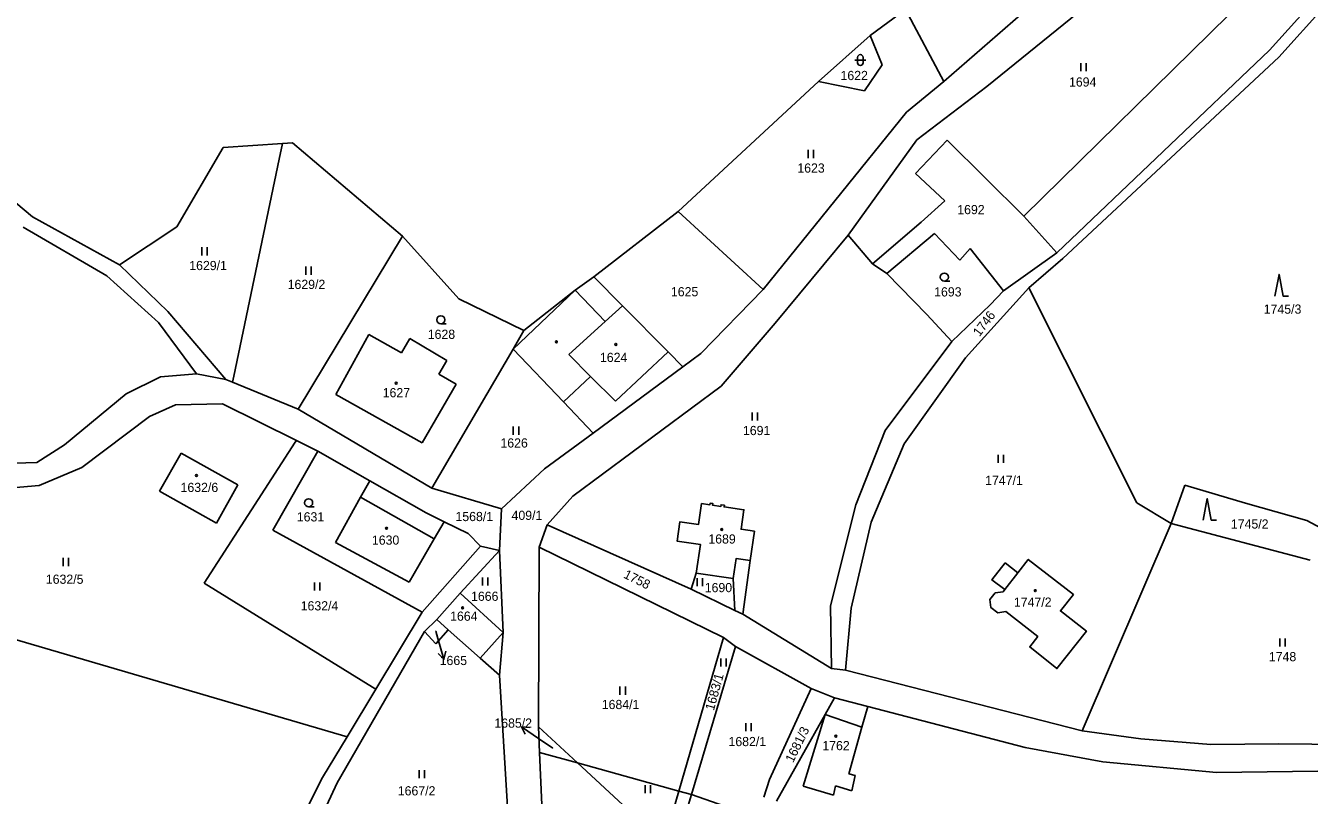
# Model space of a CAD drawing. Extents: x -670359 to -668019, y -978807 to -976674.
# Drawn here: x -669138.3 to -668901.1, y -978192.9 to -978050.6 of the extents above; entities that cross this region are included whole.
import ezdxf

# ---------------------------------------------------------------- set-up
doc = ezdxf.new("R2010")
doc.units = 0
for name, color, linetype in [('Hranice parcel', 7, 'Continuous'), ('Parcelní čísla', 7, 'Continuous'), ('Vnitřní kresba', 7, 'Continuous'), ('Značky budov', 7, 'Continuous'), ('Značky kultur', 7, 'Continuous')]:
    doc.layers.add(name, color=color, linetype=linetype)

msp = doc.modelspace()

# ---------------------------------------------------------------- linework, layer by layer
at = {"layer": 'Hranice parcel'}
for points in [[(-668936, -978032.58), (-668968.61, -978060.99)], [(-668908.45, -978055.15), (-668888.87, -978033.49)], [(-668930.88, -978037.71), (-668960.68, -978061.9)], [(-668906.72, -978056.46), (-668898.28, -978047.1)], [(-668975.67, -978047.64), (-668982.21, -978052.45)], [(-668968.61, -978060.99), (-668975.67, -978047.64)], [(-668953.8, -978085.85), (-668915.95, -978048.61)], [(-668982.21, -978052.45), (-668991.74, -978060.98)], [(-668980.02, -978057.91), (-668982.21, -978052.45)], [(-668947.71, -978092.62), (-668908.45, -978055.15)], [(-668946.62, -978093.71), (-668906.72, -978056.46)], [(-668983.27, -978062.67), (-668980.02, -978057.91)], [(-668991.74, -978060.98), (-669017.69, -978085.02)], [(-668991.74, -978060.98), (-668983.27, -978062.67)], [(-668975.47, -978066.6), (-668968.61, -978060.99)], [(-668960.68, -978061.9), (-668973.6, -978071.73)], [(-668975.47, -978066.6), (-669001.99, -978099.42)], [(-669153.63, -978072.03), (-669136.97, -978085.97)], [(-669110.34, -978087.85), (-669101.78, -978073.15)], [(-669101.78, -978073.15), (-669090.82, -978072.45)], [(-669090.82, -978072.45), (-669091.42, -978075.32)], [(-669088.96, -978072.33), (-669090.82, -978072.45)], [(-669088.96, -978072.33), (-669068.65, -978089.58)], [(-668986.28, -978089.35), (-668973.6, -978071.73)], [(-668967.97, -978071.78), (-668973.84, -978077.99)], [(-668967.97, -978071.78), (-668953.8, -978085.85)], [(-669091.42, -978075.32), (-669099.81, -978115.46)], [(-668973.84, -978077.99), (-668968.41, -978083.05)], [(-668968.41, -978083.05), (-668972.8, -978086.97)], [(-669017.69, -978085.02), (-669033.27, -978097.05)], [(-669017.69, -978085.02), (-669001.99, -978099.42)], [(-669136.97, -978085.97), (-669120.9, -978094.86)], [(-668981.81, -978094.65), (-668972.8, -978086.97)], [(-668953.8, -978085.85), (-668947.71, -978092.62)], [(-669123.24, -978096.91), (-669138.75, -978087.87)], [(-669120.9, -978094.86), (-669110.34, -978087.85)], [(-669068.65, -978089.58), (-669087.88, -978121.53)], [(-669058.21, -978101.14), (-669068.65, -978089.58)], [(-668986.28, -978089.35), (-668999.74, -978105.61)], [(-668981.81, -978094.65), (-668986.28, -978089.35)], [(-668970.35, -978089.09), (-668979.15, -978096.47)], [(-668965.63, -978093.97), (-668970.35, -978089.09)], [(-668963.76, -978091.85), (-668965.63, -978093.97)], [(-668957.56, -978099.63), (-668963.76, -978091.85)], [(-669120.9, -978094.86), (-669112.02, -978103.51)], [(-668979.15, -978096.47), (-668981.81, -978094.65)], [(-668957.56, -978099.63), (-668947.71, -978092.62)], [(-668952.92, -978099.08), (-668946.62, -978093.71)], [(-669113.72, -978105.49), (-669123.24, -978096.91)], [(-669033.27, -978097.05), (-669036.74, -978099.53)], [(-669033.27, -978097.05), (-669027.96, -978102.42)], [(-668971.73, -978104.03), (-668979.15, -978096.47)], [(-669036.74, -978099.53), (-669046.18, -978107.02)], [(-669001.99, -978099.42), (-669013.49, -978111.22)], [(-668964.59, -978112.07), (-668952.92, -978099.08)], [(-668960.07, -978102.25), (-668957.56, -978099.63)], [(-668952.92, -978099.08), (-668932.95, -978138.87)], [(-669046.18, -978107.02), (-669058.21, -978101.14)], [(-669112.02, -978103.51), (-669101.27, -978116.03)], [(-669027.96, -978102.42), (-669019.57, -978110.91)], [(-668967.11, -978109), (-668971.73, -978104.03)], [(-668967.11, -978109), (-668960.07, -978102.25)], [(-669106.7, -978115.01), (-669113.72, -978105.49)], [(-668999.74, -978105.61), (-669009.75, -978117.26)], [(-669080.97, -978118.81), (-669074.84, -978107.75)], [(-669074.84, -978107.75), (-669068.84, -978111.15)], [(-669068.84, -978111.15), (-669067.25, -978108.48)], [(-669067.25, -978108.48), (-669060.41, -978112.55)], [(-669046.18, -978107.02), (-669048.18, -978110.44)], [(-668979.46, -978125.5), (-668967.11, -978109)], [(-669048.18, -978110.44), (-669063.22, -978136.11)], [(-669038.91, -978120.18), (-669048.18, -978110.44)], [(-669019.57, -978110.91), (-669016.82, -978113.68)], [(-669013.49, -978111.22), (-669016.82, -978113.68)], [(-669060.41, -978112.55), (-669061.91, -978115.07)], [(-669016.82, -978113.68), (-669033.42, -978125.96)], [(-668975.91, -978127.95), (-668964.59, -978112.07)], [(-669113.35, -978115.58), (-669119.71, -978118.71)], [(-669106.7, -978115.01), (-669113.35, -978115.58)], [(-669101.27, -978116.03), (-669106.7, -978115.01)], [(-669101.27, -978116.03), (-669100.03, -978116.54)], [(-669099.81, -978115.46), (-669100.03, -978116.54)], [(-669061.91, -978115.07), (-669058.69, -978116.89)], [(-669087.88, -978121.53), (-669100.03, -978116.54)], [(-669058.69, -978116.89), (-669064.97, -978127.78)], [(-669009.75, -978117.26), (-669037.14, -978137.6)], [(-669119.71, -978118.71), (-669131.09, -978128.1)], [(-669110.6, -978120.73), (-669115.35, -978122.91)], [(-669101.88, -978120.58), (-669110.6, -978120.73)], [(-669101.88, -978120.58), (-669088.24, -978127.33)], [(-669064.97, -978127.78), (-669080.97, -978118.81)], [(-669038.91, -978120.18), (-669033.42, -978125.96)], [(-669115.35, -978122.91), (-669127.86, -978132.3)], [(-669087.88, -978121.53), (-669063.22, -978136.11)], [(-668984.84, -978139.2), (-668979.46, -978125.5)], [(-669131.09, -978128.1), (-669136.17, -978131.41)], [(-669088.24, -978127.33), (-669088.45, -978127.66), (-669105.26, -978153.68)], [(-669084.28, -978129.29), (-669088.24, -978127.33)], [(-669033.42, -978125.96), (-669042.37, -978132.58)], [(-668982, -978142.4), (-668975.91, -978127.95)], [(-669109.54, -978129.67), (-669113.51, -978136.69)], [(-669099.03, -978135.53), (-669109.54, -978129.67)], [(-669084.28, -978129.29), (-669092.6, -978143.88)], [(-669074.66, -978134.76), (-669084.28, -978129.29)], [(-669136.17, -978131.41), (-669171.08, -978132.47)], [(-669127.86, -978132.3), (-669135.74, -978135.65)], [(-669042.37, -978132.58), (-669050.32, -978139.97)], [(-669074.66, -978134.76), (-669076.36, -978137.81)], [(-669064.25, -978140.69), (-669074.66, -978134.76)], [(-669135.74, -978135.65), (-669147.91, -978136.72)], [(-669113.51, -978136.69), (-669103, -978142.62)], [(-669103, -978142.62), (-669099.03, -978135.53)], [(-669063.22, -978136.11), (-669050.32, -978139.97)], [(-669037.14, -978137.6), (-669041.92, -978142.9)], [(-668926.62, -978142.66), (-668924.09, -978135.6)], [(-668924.09, -978135.6), (-668912.84, -978138.91)], [(-669076.36, -978137.81), (-669081.01, -978146.16)], [(-669050.32, -978139.97), (-669050.69, -978147.69)], [(-669004.38, -978149.51), (-669003.6, -978144.11), (-669006.07, -978143.74), (-669005.55, -978140.14), (-669009.2, -978139.61), (-669009.16, -978139.31), (-669009.75, -978139.22), (-669009.79, -978139.52), (-669011.32, -978139.3), (-669011.28, -978139), (-669011.78, -978138.93), (-669011.82, -978139.22), (-669013.35, -978139), (-669013.91, -978142.85), (-669017.37, -978142.35), (-669017.88, -978145.91), (-669013.59, -978146.53), (-669014.36, -978151.86)], [(-668989.56, -978157.87), (-668984.84, -978139.2)], [(-668932.95, -978138.87), (-668926.62, -978142.66)], [(-668912.84, -978138.91), (-668901.51, -978142.11)], [(-669060.94, -978142.34), (-669064.25, -978140.69)], [(-669062.76, -978145.48), (-669060.94, -978142.34)], [(-669056.5, -978144.55), (-669060.94, -978142.34)], [(-668901.51, -978142.11), (-668887.86, -978149.46)], [(-669092.6, -978143.88), (-669064.98, -978159.05)], [(-669054.2, -978146.87), (-669056.5, -978144.55)], [(-669041.92, -978142.9), (-669043.4, -978147.05)], [(-669015.31, -978154.79), (-669041.92, -978142.9)], [(-668985.72, -978158.34), (-668982, -978142.4)], [(-668943.05, -978181.01), (-668926.62, -978142.66)], [(-668926.62, -978142.66), (-668900.88, -978149.43)], [(-669081.01, -978146.16), (-669067.4, -978153.51)], [(-669067.4, -978153.51), (-669062.76, -978145.48)], [(-669064.98, -978159.05), (-669054.2, -978146.87)], [(-669050.69, -978147.69), (-669054.2, -978146.87)], [(-669043.4, -978147.05), (-669043.51, -978180.24)], [(-669009.32, -978163.73), (-669043.4, -978147.05)], [(-669057.98, -978155.53), (-669050.69, -978147.69)], [(-669050.05, -978162.81), (-669050.69, -978147.69)], [(-668954.92, -978151.78), (-668953, -978149.32), (-668944.66, -978155.81), (-668947.06, -978158.83), (-668942.27, -978162.6), (-668947.71, -978169.5), (-668952.73, -978165.5), (-668951.24, -978163.59), (-668957.15, -978158.97), (-668958.64, -978159.2), (-668959.89, -978158.23), (-668960.09, -978156.73), (-668959.11, -978155.5), (-668957.64, -978155.29), (-668957.33, -978154.9)], [(-669187.92, -978150.12), (-669122.96, -978169.18)], [(-669005.75, -978159.45), (-669004.38, -978149.51)], [(-668957.33, -978154.9), (-668959.71, -978153.11), (-668957.27, -978149.94)], [(-668957.27, -978149.94), (-668954.92, -978151.78)], [(-669073.56, -978173.31), (-669074.15, -978172.95), (-669105.26, -978153.68)], [(-669014.36, -978151.86), (-669015.31, -978154.79)], [(-669014.36, -978151.86), (-669007.5, -978152.86)], [(-669007.5, -978152.86), (-669007.23, -978158.77)], [(-669062.27, -978160.44), (-669057.98, -978155.53)], [(-669050.05, -978162.81), (-669057.98, -978155.53)], [(-669007.23, -978158.77), (-669015.31, -978154.79)], [(-669005.75, -978159.45), (-669007.23, -978158.77)], [(-668989.37, -978169.46), (-668989.56, -978157.87)], [(-668986.79, -978169.76), (-668985.72, -978158.34)], [(-669064.98, -978159.05), (-669073.56, -978173.31)], [(-669064.54, -978162.65), (-669062.27, -978160.44)], [(-669060.21, -978162.3), (-669062.27, -978160.44)], [(-668989.37, -978169.46), (-669005.75, -978159.45)], [(-669080.68, -978190.63), (-669064.54, -978162.65)], [(-669062.48, -978164.92), (-669064.54, -978162.65)], [(-669060.21, -978162.3), (-669062.48, -978164.92)], [(-669054.26, -978167.56), (-669060.21, -978162.3)], [(-669050.69, -978170.72), (-669050.05, -978162.81)], [(-669017.58, -978192.13), (-669009.32, -978163.73)], [(-669015.24, -978192.78), (-669007.09, -978165.43)], [(-669007.09, -978165.43), (-669009.32, -978163.73)], [(-668993.09, -978173.18), (-669007.09, -978165.43)], [(-669050.69, -978170.72), (-669054.26, -978167.56)], [(-669122.96, -978169.18), (-669078.86, -978182.12)], [(-669047.23, -978227.57), (-669050.69, -978170.72)], [(-668989.37, -978169.46), (-668986.79, -978169.76)], [(-668986.79, -978169.76), (-668943.05, -978181.01)], [(-669000.79, -978189.98), (-668993.09, -978173.18)], [(-668988.8, -978174.92), (-668993.09, -978173.18)], [(-669073.56, -978173.31), (-669078.86, -978182.12)], [(-668990.54, -978177.97), (-668988.8, -978174.92)], [(-668982.66, -978176.52), (-668988.8, -978174.92)], [(-668982.66, -978176.52), (-668983.74, -978180.33)], [(-668953.59, -978184.1), (-668982.66, -978176.52)], [(-669043.51, -978180.24), (-669043.31, -978184.98)], [(-669036.28, -978186.94), (-669043.51, -978180.24)], [(-668999.54, -978194.01), (-668990.54, -978177.97)], [(-668994.61, -978191.26), (-668990.54, -978177.97)], [(-669083.39, -978189.65), (-669078.86, -978182.12)], [(-668983.74, -978180.33), (-668986.17, -978188.97)], [(-668943.05, -978181.01), (-668932.19, -978182.48)], [(-668932.19, -978182.48), (-668919.24, -978183.51)], [(-669036.28, -978186.94), (-669043.31, -978184.98)], [(-669043.31, -978184.98), (-669042.35, -978207.13)], [(-668939.22, -978186.75), (-668953.59, -978184.1)], [(-668919.24, -978183.51), (-668906.67, -978183.41)], [(-668906.67, -978183.41), (-668894.51, -978183.54)], [(-669017.58, -978192.13), (-669036.28, -978186.94)], [(-669020.36, -978201.68), (-669036.28, -978186.94)], [(-668918.21, -978188.72), (-668939.22, -978186.75)], [(-669093.61, -978209.85), (-669083.39, -978189.65)], [(-668986.17, -978188.97), (-668984.97, -978189.27)], [(-668984.97, -978189.27), (-668985.58, -978192.1)], [(-668894.83, -978188.42), (-668918.21, -978188.72)], [(-669090.18, -978211.09), (-669080.68, -978190.63)], [(-669020.36, -978201.68), (-669017.58, -978192.13)], [(-669015.24, -978192.78), (-669017.58, -978192.13)], [(-669001.87, -978193.24), (-669000.79, -978189.98)], [(-668988.96, -978192.92), (-668994.61, -978191.26)], [(-668988.61, -978191.16), (-668988.96, -978192.92)], [(-668985.58, -978192.1), (-668988.61, -978191.16)], [(-669018.05, -978202.19), (-669015.24, -978192.78)], [(-669003.12, -978197.04), (-669015.24, -978192.78)]]:
    msp.add_lwpolyline(points, dxfattribs=at)
at = {"layer": 'Parcelní čísla'}
for p, q in [((-669062.49, -978162.57), (-669062.09, -978163.92)), ((-669060.62, -978166.3), (-669060.98, -978167.76)), ((-669045.97, -978181.64), (-669046.62, -978180.29)), ((-669040.87, -978184.23), (-669043.32, -978182.55))]:
    msp.add_line(p, q, dxfattribs=at)
for points in [[(-669062.09, -978163.92), (-669060.98, -978167.76), (-669062.06, -978166.72)], [(-669043.32, -978182.55), (-669046.62, -978180.29), (-669045.12, -978180.4)]]:
    msp.add_lwpolyline(points, dxfattribs=at)
at = {"layer": 'Vnitřní kresba'}
for points in [[(-669048.18, -978110.44), (-669036.74, -978099.53)], [(-669036.74, -978099.53), (-669031.19, -978105.35)], [(-669031.19, -978105.35), (-669027.96, -978102.42)], [(-669031.19, -978105.35), (-669037.91, -978111.42)], [(-669037.91, -978111.42), (-669033.86, -978115.48)], [(-669029.27, -978120.08), (-669019.57, -978110.91)], [(-669033.86, -978115.48), (-669038.91, -978120.18)], [(-669033.86, -978115.48), (-669029.27, -978120.08)], [(-669076.36, -978137.81), (-669062.76, -978145.48)], [(-669007.5, -978152.86), (-669006.95, -978149.13), (-669004.38, -978149.51)], [(-668957.33, -978154.9), (-668954.92, -978151.78)], [(-669054.26, -978167.56), (-669050.05, -978162.81)], [(-668983.74, -978180.33), (-668990.54, -978177.97)]]:
    msp.add_lwpolyline(points, dxfattribs=at)
at = {"layer": 'Značky budov'}
for centre in [(-669029.19, -978109.56), (-669069.79, -978116.74), (-669106.71, -978133.79), (-669071.57, -978143.56), (-669009.65, -978143.78), (-668951.7, -978155.08), (-669057.52, -978158.27), (-668988.55, -978181.98)]:
    msp.add_circle(centre, 0.175, dxfattribs=at)
at = {"layer": 'Značky kultur'}
for p, q in [((-668984.53, -978056.5), (-668984.53, -978057.5)), ((-668983.53, -978056.5), (-668983.53, -978057.5)), ((-668985.03, -978057), (-668983.03, -978057)), ((-668943.29, -978057.57), (-668943.29, -978059.07)), ((-668942.29, -978059.07), (-668942.29, -978057.57)), ((-668993.67, -978073.61), (-668993.67, -978075.11)), ((-668992.67, -978075.11), (-668992.67, -978073.61)), ((-669105.7, -978091.6), (-669105.7, -978093.1)), ((-669104.7, -978093.1), (-669104.7, -978091.6)), ((-669086.49, -978095.18), (-669086.49, -978096.68)), ((-669085.49, -978096.68), (-669085.49, -978095.18)), ((-668968.5, -978097.87), (-668967.5, -978097.87)), ((-669061.55, -978105.76), (-669060.55, -978105.76)), ((-669004.04, -978122.13), (-669004.04, -978123.63)), ((-669003.04, -978123.63), (-669003.04, -978122.13)), ((-669048.16, -978124.75), (-669048.16, -978126.25)), ((-669047.16, -978126.25), (-669047.16, -978124.75)), ((-668958.59, -978129.96), (-668958.59, -978131.46)), ((-668957.59, -978131.46), (-668957.59, -978129.96)), ((-669085.98, -978139.59), (-669084.98, -978139.59)), ((-669131.33, -978149.04), (-669131.33, -978150.54)), ((-669130.33, -978150.54), (-669130.33, -978149.04)), ((-669084.92, -978153.55), (-669084.92, -978155.05)), ((-669083.92, -978155.05), (-669083.92, -978153.55)), ((-669053.84, -978152.66), (-669053.84, -978154.16)), ((-669052.84, -978154.16), (-669052.84, -978152.66)), ((-669014.17, -978152.75), (-669014.17, -978154.25)), ((-669013.17, -978154.25), (-669013.17, -978152.75)), ((-668906.54, -978163.94), (-668906.54, -978165.44)), ((-668905.54, -978165.44), (-668905.54, -978163.94)), ((-669009.83, -978167.61), (-669009.83, -978169.11)), ((-669008.83, -978169.11), (-669008.83, -978167.61)), ((-669028.45, -978172.82), (-669028.45, -978174.32)), ((-669027.45, -978174.32), (-669027.45, -978172.82)), ((-669005.21, -978179.58), (-669005.21, -978181.08)), ((-669004.21, -978181.08), (-669004.21, -978179.58)), ((-669065.58, -978188.27), (-669065.58, -978189.77)), ((-669064.58, -978189.77), (-669064.58, -978188.27)), ((-669023.8, -978191.02), (-669023.8, -978192.52)), ((-669022.8, -978192.52), (-669022.8, -978191.02))]:
    msp.add_line(p, q, dxfattribs=at)
for points in [[(-668907.41, -978100.64), (-668906.66, -978096.64), (-668905.91, -978100.64), (-668904.91, -978100.64)], [(-668920.69, -978142.05), (-668919.94, -978138.05), (-668919.19, -978142.05), (-668918.19, -978142.05)]]:
    msp.add_lwpolyline(points, dxfattribs=at)
for centre, radius in [((-668968.5, -978097.12), 0.75), ((-669061.55, -978105.01), 0.75), ((-669040.2, -978109.1), 0.175), ((-669029.19, -978109.56), 0.175), ((-669069.79, -978116.74), 0.175), ((-669106.71, -978133.79), 0.175), ((-669085.98, -978138.84), 0.75), ((-669071.57, -978143.56), 0.175), ((-669009.65, -978143.78), 0.175), ((-668951.7, -978155.08), 0.175), ((-669057.52, -978158.27), 0.175), ((-668988.55, -978181.98), 0.175)]:
    msp.add_circle(centre, radius, dxfattribs=at)
for centre, start, end in [((-668984.03, -978056.5), 0, 180), ((-668984.03, -978057.5), 180, 0)]:
    msp.add_arc(centre, 0.5, start, end, dxfattribs=at)

# ---------------------------------------------------------------- texts
at = {"layer": 'Parcelní čísla'}
for s, height, p in [('1622', 1.7, (-668987.69, -978060.7)), ('1694', 1.7, (-668945.47, -978061.9)), ('1623', 1.7, (-668995.67, -978077.81)), ('1692', 1.7, (-668966.12, -978085.49)), ('1629/1', 1.7, (-669108.03, -978095.83)), ('1629/2', 1.7, (-669089.85, -978099.32)), ('1625', 1.7, (-669019.03, -978100.67)), ('1693', 1.7, (-668970.39, -978100.7)), ('1745/3', 1.7, (-668909.49, -978103.89)), ('1628', 1.7, (-669063.96, -978108.54)), ('1624', 1.7, (-669032.14, -978112.81)), ('1627', 1.7, (-669072.29, -978119.34)), ('1691', 1.7, (-669005.72, -978126.33)), ('1626', 1.7, (-669050.53, -978128.63)), ('1632/6', 1.7, (-669109.64, -978136.85)), ('1747/1', 1.7, (-668960.96, -978135.54)), ('1631', 1.7, (-669088.16, -978142.29)), ('1568/1', 1.7, (-669058.84, -978142.23)), ('409/1', 1.7, (-669048.48, -978142.01)), ('1745/2', 1.7, (-668915.56, -978143.61)), ('1689', 1.7, (-669012.11, -978146.38)), ('1630', 1.7, (-669074.28, -978146.59)), ('1632/5', 1.7, (-669134.53, -978153.82)), ('1690', 1.7, (-669012.78, -978155.37)), ('1666', 1.7, (-669055.96, -978156.97)), ('1747/2', 1.7, (-668955.65, -978158.06)), ('1632/4', 1.7, (-669087.44, -978158.74)), ('1664', 1.7, (-669059.83, -978160.65)), ('1665', 0.1, (-669062.64, -978162.57)), ('1665', 1.7, (-669061.76, -978168.84)), ('1748', 1.7, (-668908.54, -978168.14)), ('1684/1', 1.7, (-669031.81, -978176.98)), ('1685/2', 1.7, (-669051.65, -978180.42)), ('1682/1', 1.7, (-669008.39, -978183.83)), ('1685/2', 0.1, (-669041.11, -978184.23)), ('1762', 1.7, (-668991.05, -978184.58)), ('1667/2', 1.7, (-669069.5, -978192.94))]:
    msp.add_text(s, height=height, dxfattribs=at).set_placement(p)
for s, rotation, p in [('1746', 53.0742, (-668962.01, -978108.23)), ('1758', 333.435, (-669027.92, -978152.63)), ('1683/1', 74.5826, (-669011.1, -978177.36)), ('1681/3', 63.9, (-668996.46, -978187.01))]:
    msp.add_text(s, height=1.7, rotation=rotation, dxfattribs=at).set_placement(p)

doc.saveas('drawing.dxf')
